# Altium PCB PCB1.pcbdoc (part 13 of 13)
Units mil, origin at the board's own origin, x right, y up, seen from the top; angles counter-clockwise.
Board outline 5895.51 x 5895.51 mil, 8 copper layers (Top Layer, L2_GND1, L3_SIG1, L4_GND2, L5_PWR, L6_SIG2, L7_GND3, Bottom Layer), stack 63.761 mil thick; 673 components, 558 nets, 2797 pads, 1861 vias.
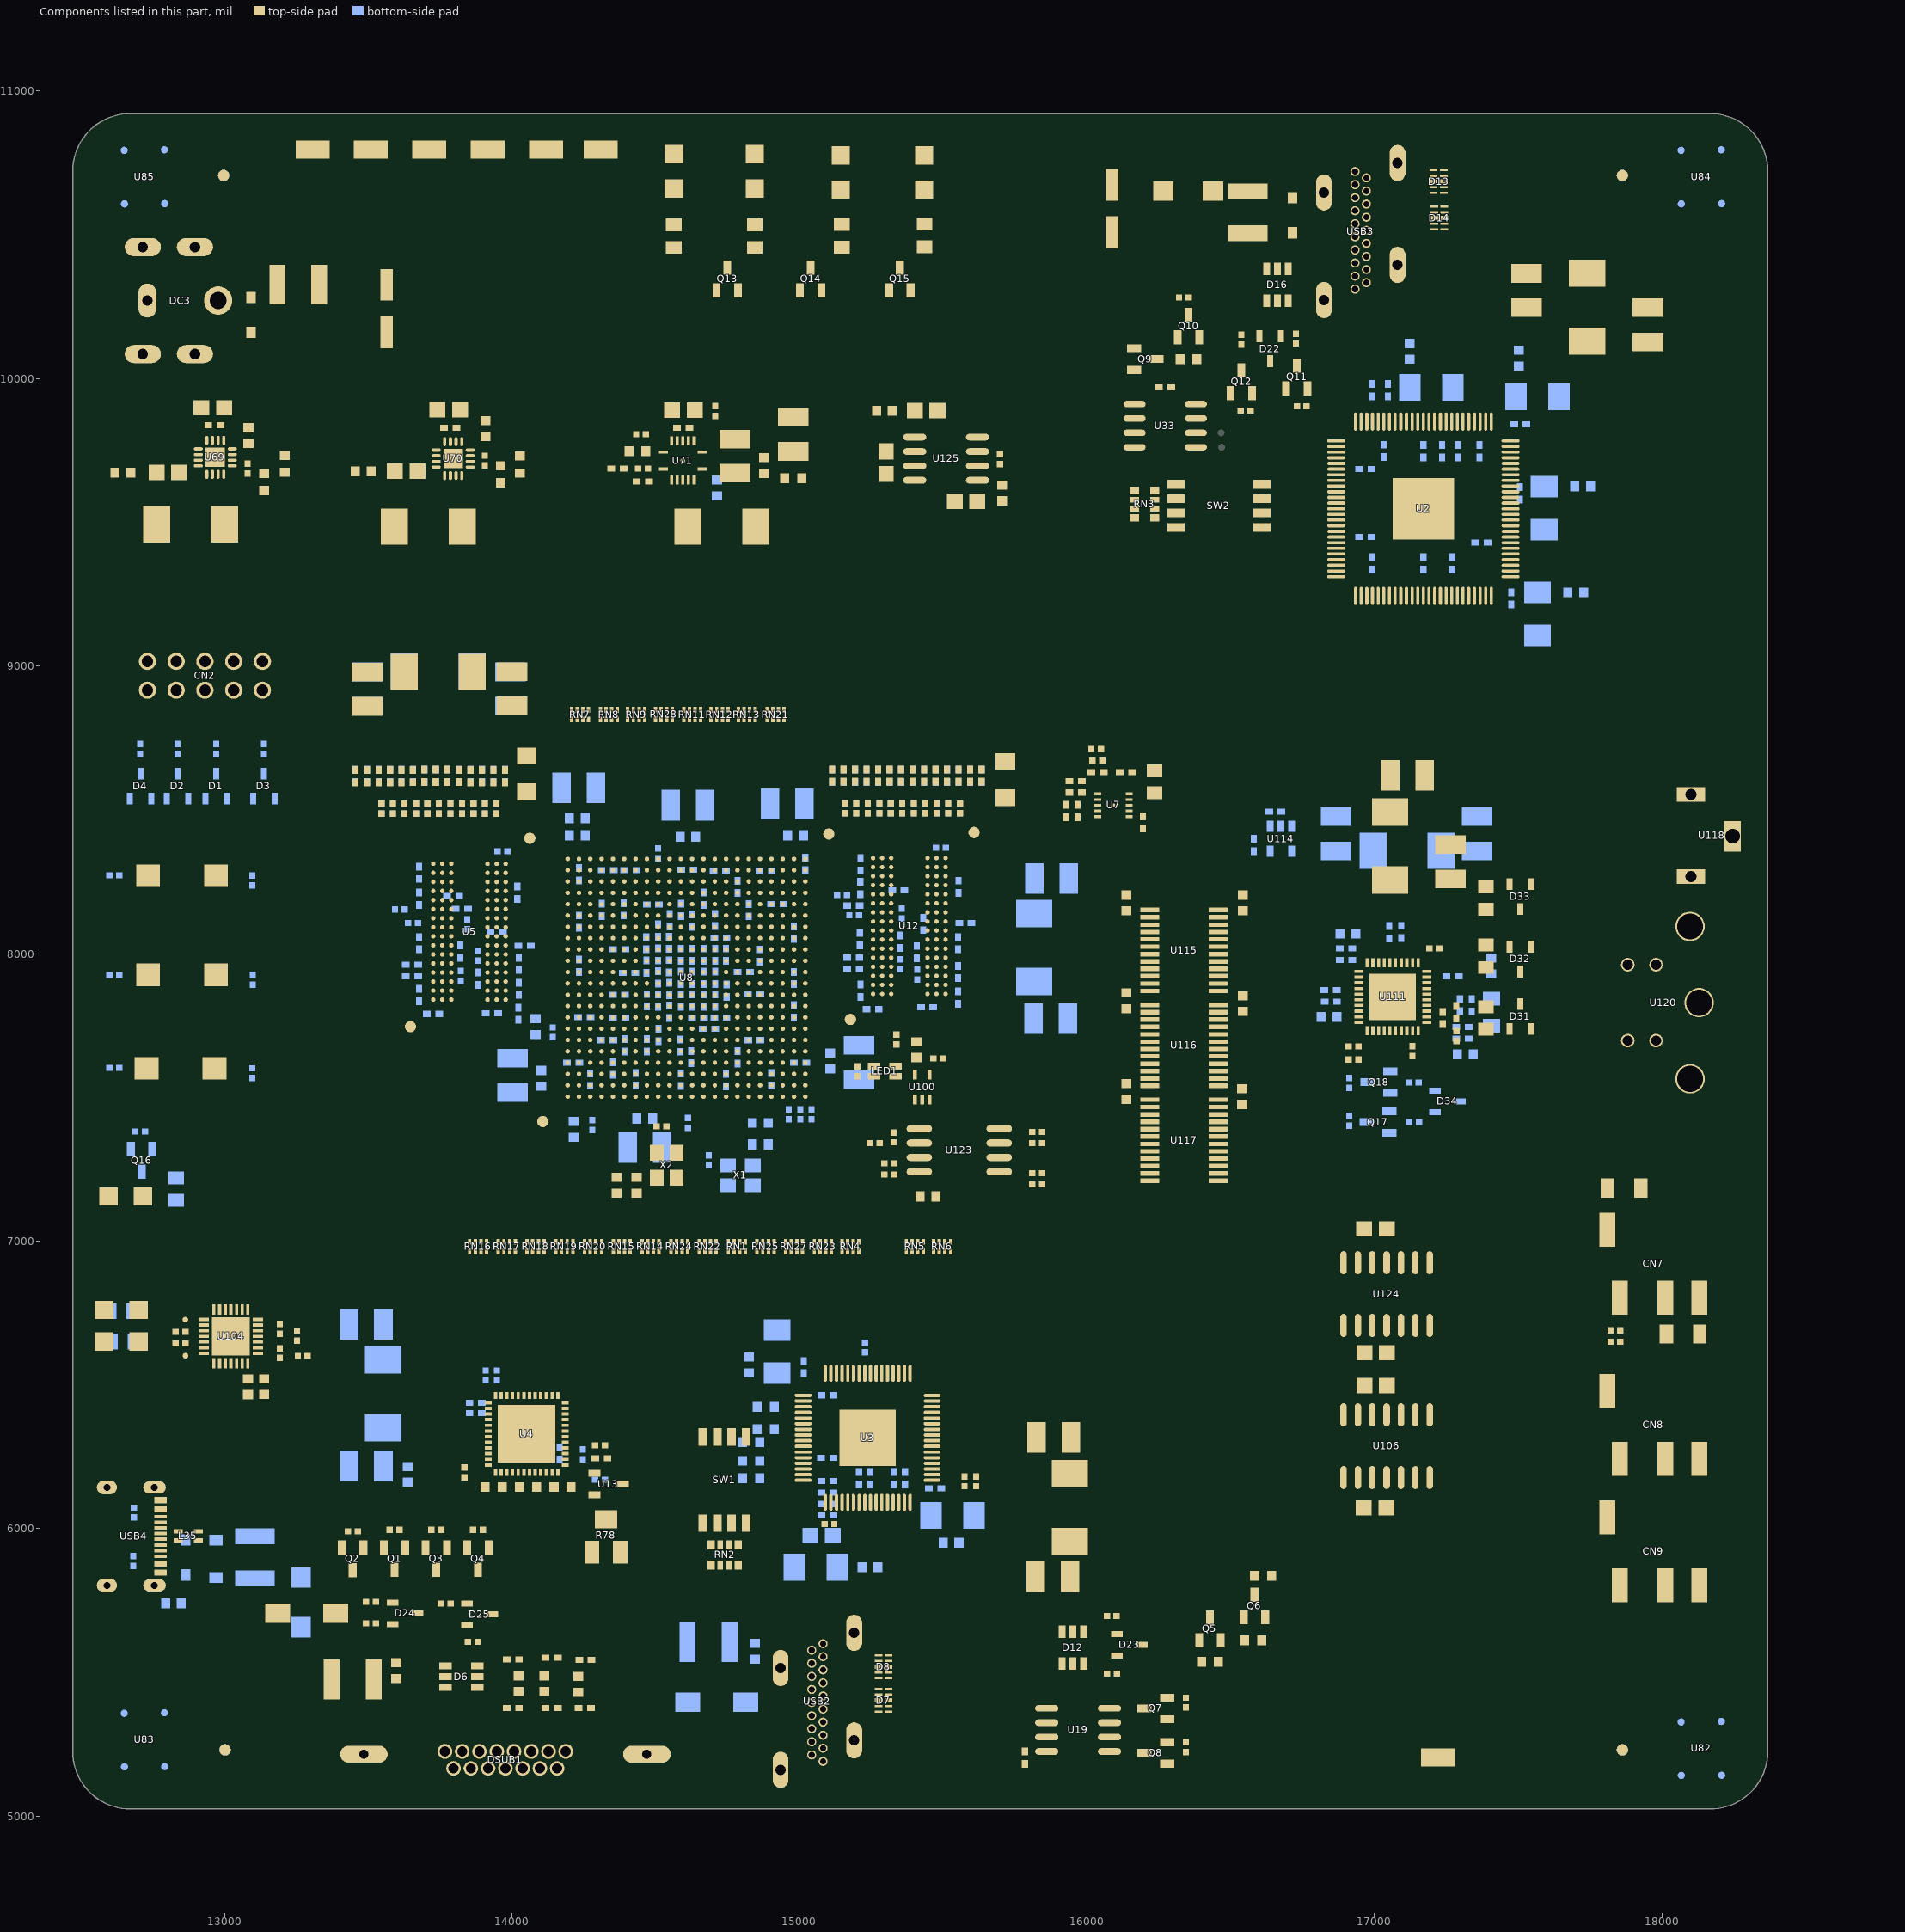
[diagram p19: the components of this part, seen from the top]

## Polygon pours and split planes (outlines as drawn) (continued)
FPGA_3V3 on Top Layer (solid, remove dead copper, pour order 248): 44 vertices, not listed, extent 13951.36,7055 15457.36,7588
VCC_1V5 on L5_PWR (solid, remove dead copper): 27 vertices, not listed, extent 14858.1,7420 16419.36,8688
VCC_1V5 on L5_PWR (solid, remove dead copper): 41 vertices, not listed, extent 13362.36,8615 15999.18,9852
VTT_DDR3 on Top Layer (solid, remove dead copper, pour order 254): 14010.1,8511.16 15163.52,8511.16 15168.36,8516 15136.02,8548.34 15136.02,8609.82 14002.54,8609.82 13997.36,8615 13997.36,8523.9
GND on Bottom Layer (solid, remove dead copper, pour order 372): 14724.36,7158 14870.36,7158 14876.36,7164 14876.36,7362.23 14880.74,7366.62 14934.74,7366.62 15032.36,7269 15215.26,7269 15215.26,7132.09 14729.45,7132.09 14724.36,7127
GND on Bottom Layer (solid, remove dead copper, pour order 374): 19 vertices, not listed, extent 14614.36,8368 15138.87,8737.52
GND on Bottom Layer (solid, remove dead copper, pour order 376): 14075.42,8623.83 14130.39,8623.83 14130.39,8382.52 14137.43,8375.49 14226.2,8375.49 14228.9,8378.19 14228.9,8637.45 14138.36,8728 14068.88,8728 14068.88,8630.36
GND on Bottom Layer (solid, remove dead copper, pour order 378): 14560.16,7463.2 14567.36,7456 14567.36,7149 14562.36,7144 13784.36,7144 13780.36,7140 13780.36,7225 13784.36,7229 14469.28,7229 14475.36,7235.08 14475.36,7459.36 14477.26,7463.2
VCC_AUX on Bottom Layer (solid, remove dead copper, pour order 380): 14238.39,8383.06 14328.03,8383.06 14328.03,8740.33 14317.36,8751 14188.36,8751 14186.36,8753 14186.36,9080 14145.66,9080 14145.66,8744.69 14205.36,8685 14239.36,8685 14239.36,8384.03
VCC_AUX on L3_SIG1 (solid, remove dead copper): 14439.12,8120.4 14783.2,8120.4 14783.2,7940.28 14439.12,7940.28
VCC_AUX on L5_PWR (solid, remove dead copper): 14238.39,8383.06 14424.26,8383.06 14436.84,8370.49 14436.84,8062.48 14436.36,8062 14489.36,8062 14491.36,8060 14491.36,8505.92 14478.68,8518.59 14232.36,8518.59 14238.39,8512.55
VDD_DDR3 on L5_PWR (solid, remove dead copper): 15550.36,8353 15746.64,8353 15746.64,8091.5 15550.36,8091.5
VDD_DDR3 on L5_PWR (solid, remove dead copper): 18 vertices, not listed, extent 13659.74,7795.97 14178.36,9189.39
VDD_DDR3 on Top Layer (solid, remove dead copper, pour order 274): 19 vertices, not listed, extent 14050.36,8099.88 16552.67,9195.38
GND on Top Layer (solid, remove dead copper, pour order 276): 18 vertices, not listed, extent 14414.26,7125.9 15214.94,7456
GND on Bottom Layer (solid, remove dead copper, pour order 394): 14627.36,6731 14998.47,6731 14998.47,6672.7 14627.36,6672.7
410_DVDD on Bottom Layer (solid, remove dead copper, pour order 396): 24 vertices, not listed, extent 15037.51,6230 15131.36,6501
410_TVDD on Bottom Layer (solid, remove dead copper, pour order 398): 15190.29,6164.93 15385,6164.93 15385,6125.35 15190.29,6125.35
GND on Bottom Layer (solid, remove dead copper, pour order 400): 14954.36,5806 15065.36,5806 15066.36,5805 15077.36,5816 15077.36,6050.28 15089.72,6062.64 15089.72,6188.28 14983.64,6188.28 14980.36,6185 14980.36,5931 14968.36,5919 14889.36,5919 14889.36,5810 14889.41,5802 14950.36,5802
GND on Top Layer (solid, remove dead copper, pour order 286): 13004.56,10184.84 13253.36,10184.84 13253.36,10037 13004.56,10037
GND on Bottom Layer (solid, remove dead copper, pour order 404): 10961.36,12250 20212.36,12250 20212.36,3000 10961.36,3000
GND on Top Layer (solid, remove dead copper, pour order 290): 25 vertices, not listed, extent 13770.36,7136 14546.36,7465

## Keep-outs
Board Outline Layer:
  region: 18181.49,10531.81 18321.67,10531.81 18321.67,9631.72 18181.49,9631.72
  lines w10: 12472.36,5225.49 ccw(c12672.36,5225.49) 12672.36,5025.49 18167.87,5025.49 ccw(c18167.87,5225.49) 18367.87,5225.49 18367.87,10721 ccw(c18167.87,10721) 18167.87,10921 12672.36,10921 ccw(c12672.36,10721) 12472.36,10721 12472.36,5225.49

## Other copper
Top Layer:
  drawing of 3039 lines, arcs and shapes, not listed
  text "1" at 18230.36,10404 h120
L2_GND1:
  text "2" at 18230.36,10294 h120
L3_SIG1:
  drawing of 203 lines, arcs and shapes, not listed
  text "3" at 18230.36,10184 h120
L4_GND2:
  region net 401_DVDD: 16716.6,9893.07 16708.52,9872.87 ccw(c16729.07,9893.41) 16719.74,9865.89 16727.62,9877.81 ccw(c16674.88,9851.35)
  text "4" at 18230.36,10074 h120
L5_PWR:
  region net VCC_1V2: 14452.99,8023.92 14460.06,8030.99 14459.46,8031.52 14458.88,8031.91 14457.86,8032.51 14457.45,8032.83 14457.12,8033.23 14456.89,8033.78 14456.77,8034.53 14449.45,8027.21 14450.2,8027.1 14450.75,8026.87 14451.16,8026.54 14451.48,8026.13 14452.07,8025.11 14452.47,8024.53
  region net VCC_1V2: 14486.15,8004.91 14479.08,7997.84 14479.68,7997.31 14480.26,7996.92 14481.28,7996.32 14481.7,7996 14482.03,7995.6 14482.25,7995.05 14482.37,7994.3 14489.69,8001.62 14488.94,8001.73 14488.39,8001.96 14487.99,8002.29 14487.67,8002.7 14487.07,8003.72 14486.68,8004.3
  region net FPGA_3V3: 14334.89,7590.87 14341.96,7597.94 14341.36,7598.47 14340.78,7598.86 14339.76,7599.46 14339.35,7599.78 14339.02,7600.18 14338.79,7600.73 14338.67,7601.48 14331.35,7594.16 14332.1,7594.05 14332.65,7593.82 14333.06,7593.49 14333.38,7593.08 14333.97,7592.06 14334.37,7591.48
  region net VCC_AUX: 14775.01,8076.58 14767.94,8083.65 14767.42,8083.04 14767.03,8082.46 14766.43,8081.44 14766.11,8081.03 14765.7,8080.7 14765.15,8080.47 14764.4,8080.36 14771.72,8073.04 14771.84,8073.79 14772.07,8074.34 14772.4,8074.74 14772.81,8075.06 14773.83,8075.66 14774.41,8076.05
  region net VCC_AUX: 14794.02,8227.84 14801.09,8220.77 14801.62,8221.38 14802.01,8221.96 14802.61,8222.98 14802.93,8223.39 14803.33,8223.72 14803.88,8223.95 14804.63,8224.06 14797.31,8231.38 14797.2,8230.63 14796.97,8230.08 14796.64,8229.68 14796.23,8229.36 14795.2,8228.76 14794.63,8228.37
  region net VCC_AUX: 14767.05,8082.76 14774.12,8075.69 14777.66,8086.29 14787.36,8102.01
  region net VDD_DDR3_REF: 15099.36,8321.65 15099.36,8336.65 ccw(c15099.36,8427.9) 15159.36,8359.15 15159.36,8299.15 ccw(c15099.36,8230.4)
  text "5" at 18230.36,9964 h120
L6_SIG2:
  drawing of 394 lines, arcs and shapes, not listed
  text "6" at 18230.36,9854 h120
L7_GND3:
  text "7" at 18230.36,9744 h120
Bottom Layer:
  drawing of 999 lines, arcs and shapes, not listed
  text "8" at 18280.19,9634.54 h120

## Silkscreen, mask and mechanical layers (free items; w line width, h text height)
Top Silkscreen Layer:
  drawing of 43 lines, arcs and shapes, not listed
  text "DVI_IN" at 16325.06,10727.32 h120
  text "5V" at 14767.27,10641.73 h120 r90
  text "1V5" at 15347.27,10593.55 h120 r90
  text "3V3" at 15052.27,10588.55 h120 r90
  text "1V2" at 15637.27,10588.55 h120 r90
  text "5V" at 13574.92,10568.08 h120 r90
  text "1V2" at 14192.79,10491.87 h120 r90
  text "3V3" at 13779.26,10488.91 h120 r90
  text "1V5" at 13991.27,10488.55 h120 r90
  text "N5V" at 14381.61,10479.35 h120 r90
  text "GND" at 13388.18,10453.36 h120 r90
  text "5V_IN" at 12483.36,9900 h120
  text "ST  / OCK_INV / DFO / PIXS" at 15934.36,9469 h45
  text "0" at 16549.36,9353 h60
  text "1" at 16345.36,9349 h60
  text "JTAG" at 12782.36,8601 h120
  text "CVBS" at 18001.06,8258.32 h120 r90
  text "MENU" at 13044.45,8198.09 h120
  text "+" at 13072.36,7846 h120
  text "S-VIDEO" at 17794.9,7559.71 h120 r90
  text "-" at 13073.08,7528.09 h120
  text "RX" at 12629.36,6810 h100
  text "Aduio_IN" at 17726.83,6703.74 h120 r90
  text "TX" at 12630.36,6478 h100
  text "0" at 14543.36,6273 h60
  text "1" at 14559.36,6042 h60
  text "RSET" at 14431.36,5939 h45
  text "Aduio_OUT" at 17735.47,5802.13 h120 r90
  text "MSEN / ISEL / DSEL / BSEL" at 14828.36,5731 h45 r90
  text "USB_UART" at 12487.36,5641 h100
  text "GND" at 17323.83,5124.72 h120
  text "DVI_OUT" at 14918.08,5047.52 h120 r90
  text "VGA_OUT" at 13328.26,5024.04 h120 r90
Bottom Silkscreen Layer:
  lines w10: 14155.36,7499 14156.36,7500 ; 14156.36,7662.64 14156.36,7500 ; 14164.36,7797.17 14164.36,8336 14167.36,8339 14418.36,8339 14419.36,8338 ; 14469.36,8299 14472.36,8302 14538.36,8302 14557.84,8321.48 14557.84,8359 14563.84,8365 15037.36,8365 ; 14781.36,8379 14781.36,8681 14891.36,8681 15065.36,8855 ; 15016.36,7744 15022.36,7750 15022.36,7953 ; 15027.36,8027 15028.36,8028 15028.36,8174 ; 15046.36,8248 15048.36,8250 15048.36,8340 ; 15049.36,7658 15049.36,7501 15050.36,7500 14156.36,7500 ; 15065.36,8855 15924.36,8855 15924.36,9644 15065.36,9644 15065.36,8855
  text "A" at 15050.36,8848 h80
  text "A" at 14205.36,7496 h80
  text "US_VIO_V1.0 / 2024.5.25 / BY EE" at 16402.36,6666 h120
Document Layer:
  lines w10: 20966.53,5595.13 25954.97,5595.13 ; 20966.53,5605.13 20966.53,10623.7 25954.97,10623.7 25954.97,5605.13 ; 20966.53,5823.7 25954.97,5823.7 ; 20966.53,6052.27 25954.97,6052.27 ; 20966.53,6280.84 25954.97,6280.84 ; 20966.53,6509.42 25954.97,6509.42 ; 20966.53,6737.99 25954.97,6737.99 ; 20966.53,6966.56 25954.97,6966.56 ; 20966.53,7195.13 25954.97,7195.13 ; 20966.53,7423.7 25954.97,7423.7 ; 20966.53,7652.27 25954.97,7652.27 ; 20966.53,7880.84 25954.97,7880.84 ; 20966.53,8109.42 25954.97,8109.42 ; 20966.53,8337.99 25954.97,8337.99 ; 20966.53,8566.56 25954.97,8566.56 ; 20966.53,8795.13 25954.97,8795.13 ; 20966.53,9023.7 25954.97,9023.7 ; 20966.53,9252.27 25954.97,9252.27 ; 20966.53,9480.84 25954.97,9480.84 ; 20966.53,9709.42 25954.97,9709.42 ; 20966.53,9937.99 25954.97,9937.99 ; 20966.53,10166.56 25954.97,10166.56 ; 20966.53,10395.13 25954.97,10395.13 ; 21723.69,5605.13 21723.69,10623.7 ; 22839.54,5605.13 22839.54,10623.7 ; 23966.4,5605.13 23966.4,10623.7 ; 24629.26,5605.13 24629.26,10623.7 ; 25292.12,5605.13 25292.12,10623.7
  text "图层" at 21080.82,10509.42 h80
  text "类型" at 21837.97,10509.42 h80
  text "材质" at 22953.83,10509.42 h80
  text "厚度(mm)" at 24080.69,10509.42 h80
  text "介电常数" at 24743.54,10509.42 h80
  text "损耗切线" at 25406.4,10509.42 h80
  text "顶层丝印层" at 21080.82,10280.84 h80
  text "TOP_SILK" at 21837.97,10280.84 h80
  text "-" at 22953.83,10280.84 h80
  text "0" at 24080.69,10280.84 h80
  text "0" at 24743.54,10280.84 h80
  text "0" at 25406.4,10280.84 h80
  text "顶层锡膏层" at 21080.82,10052.27 h80
  text "TOP_PASTE_MASK" at 21837.97,10052.27 h80
  text "-" at 22953.83,10052.27 h80
  text "0" at 24080.69,10052.27 h80
  text "0" at 24743.54,10052.27 h80
  text "0" at 25406.4,10052.27 h80
  text "顶层阻焊层" at 21080.82,9823.7 h80
  text "TOP_SOLDER_MASK" at 21837.97,9823.7 h80
  text "0" at 24080.69,9823.7 h80
  text "0" at 24743.54,9823.7 h80
  text "0" at 25406.4,9823.7 h80
  text "顶层" at 21080.82,9595.13 h80
  text "TOP" at 21837.97,9595.13 h80
  text "外层铜厚1oz" at 22953.83,9595.13 h80
  text "0.035" at 24080.69,9595.13 h80
  text "0" at 24743.54,9595.13 h80
  text "0" at 25406.4,9595.13 h80
  text "Dielectric1" at 21080.82,9366.56 h80
  text "SUBSTRATE" at 21837.97,9366.56 h80
  text "1080 RC67% 3.3mil" at 22953.83,9366.56 h80
  text "0.076" at 24080.69,9366.56 h80
  text "0" at 24743.54,9366.56 h80
  text "0" at 25406.4,9366.56 h80
  text "L2_GND1" at 21080.82,9137.99 h80
  text "SIGNAL" at 21837.97,9137.99 h80
  text "内层铜厚" at 22953.83,9137.99 h80
  text "0.015" at 24080.69,9137.99 h80
  text "0" at 24743.54,9137.99 h80
  text "0" at 25406.4,9137.99 h80
  text "Dielectric2" at 21080.82,8909.42 h80
  text "SUBSTRATE" at 21837.97,8909.42 h80
  text "0.3mm H/HOZ 不含铜" at 22953.83,8909.42 h80
  text "0.3" at 24080.69,8909.42 h80
  text "0" at 24743.54,8909.42 h80
  text "0" at 25406.4,8909.42 h80
  text "L3_SIG1" at 21080.82,8680.84 h80
  text "SIGNAL" at 21837.97,8680.84 h80
  text "内层铜厚" at 22953.83,8680.84 h80
  text "0.015" at 24080.69,8680.84 h80
  text "0" at 24743.54,8680.84 h80
  text "0" at 25406.4,8680.84 h80
  text "Dielectric3" at 21080.82,8452.27 h80
  text "SUBSTRATE" at 21837.97,8452.27 h80
  text "7628 RC49% 8.6mil" at 22953.83,8452.27 h80
  text "0.203" at 24080.69,8452.27 h80
  text "0" at 24743.54,8452.27 h80
  text "0" at 25406.4,8452.27 h80
  text "L4_GND2" at 21080.82,8223.7 h80
  text "SIGNAL" at 21837.97,8223.7 h80
  text "内层铜厚" at 22953.83,8223.7 h80
  text "0.015" at 24080.69,8223.7 h80
  text "0" at 24743.54,8223.7 h80
  text "0" at 25406.4,8223.7 h80
  text "Dielectric4" at 21080.82,7995.13 h80
  text "SUBSTRATE" at 21837.97,7995.13 h80
  text "0.3mm H/HOZ 不含铜" at 22953.83,7995.13 h80
  text "0.3" at 24080.69,7995.13 h80
  text "0" at 24743.54,7995.13 h80
  text "0" at 25406.4,7995.13 h80
  text "L5_PWR" at 21080.82,7766.56 h80
  text "SIGNAL" at 21837.97,7766.56 h80
  text "内层铜厚" at 22953.83,7766.56 h80
  text "0.015" at 24080.69,7766.56 h80
  text "0" at 24743.54,7766.56 h80
  text "0" at 25406.4,7766.56 h80
  text "Dielectric5" at 21080.82,7537.99 h80
  text "SUBSTRATE" at 21837.97,7537.99 h80
  text "7628 RC49% 8.6mil" at 22953.83,7537.99 h80
  text "0.203" at 24080.69,7537.99 h80
  text "0" at 24743.54,7537.99 h80
  text "0" at 25406.4,7537.99 h80
  text "L6_SIG2" at 21080.82,7309.42 h80
  text "SIGNAL" at 21837.97,7309.42 h80
  text "内层铜厚" at 22953.83,7309.42 h80
  text "0.015" at 24080.69,7309.42 h80
  text "0" at 24743.54,7309.42 h80
  text "0" at 25406.4,7309.42 h80
  text "Dielectric6" at 21080.82,7080.84 h80
  text "SUBSTRATE" at 21837.97,7080.84 h80
  text "0.3mm H/HOZ 不含铜" at 22953.83,7080.84 h80
  text "0.3" at 24080.69,7080.84 h80
  text "0" at 24743.54,7080.84 h80
  text "0" at 25406.4,7080.84 h80
  text "L7_GND3" at 21080.82,6852.27 h80
  text "SIGNAL" at 21837.97,6852.27 h80
  text "内层铜厚" at 22953.83,6852.27 h80
  text "0.015" at 24080.69,6852.27 h80
  text "0" at 24743.54,6852.27 h80
  text "0" at 25406.4,6852.27 h80
  text "Dielectric7" at 21080.82,6623.7 h80
  text "SUBSTRATE" at 21837.97,6623.7 h80
  text "1080 RC67% 3.3mil" at 22953.83,6623.7 h80
  text "0.076" at 24080.69,6623.7 h80
  text "0" at 24743.54,6623.7 h80
  text "0" at 25406.4,6623.7 h80
  text "底层" at 21080.82,6395.13 h80
  text "BOTTOM" at 21837.97,6395.13 h80
  text "外层铜厚1oz" at 22953.83,6395.13 h80
  text "0.035" at 24080.69,6395.13 h80
  text "0" at 24743.54,6395.13 h80
  text "0" at 25406.4,6395.13 h80
  text "底层阻焊层" at 21080.82,6166.56 h80
  text "BOT_SOLDER_MASK" at 21837.97,6166.56 h80
  text "0" at 24080.69,6166.56 h80
  text "0" at 24743.54,6166.56 h80
  text "0" at 25406.4,6166.56 h80
  text "底层锡膏层" at 21080.82,5937.99 h80
  text "BOT_PASTE_MASK" at 21837.97,5937.99 h80
  text "-" at 22953.83,5937.99 h80
  text "0" at 24080.69,5937.99 h80
  text "0" at 24743.54,5937.99 h80
  text "0" at 25406.4,5937.99 h80
  text "底层丝印层" at 21080.82,5709.42 h80
  text "BOT_SILK" at 21837.97,5709.42 h80
  text "-" at 22953.83,5709.42 h80
  text "0" at 24080.69,5709.42 h80
  text "0" at 24743.54,5709.42 h80
  text "0" at 25406.4,5709.42 h80
Ratline Layer:
  drawing of 38 lines, arcs and shapes, not listed
  text "Mark" at 3114.29,10142.89 h80
  text "Count" at 3627.34,10142.89 h80
  text "Size" at 4184.1,10142.89 h80
  text "Plated" at 5744.96,10142.89 h80
  text "Shape" at 6320.31,10142.89 h80
  text "Via/Pad" at 6883.77,10142.89 h80
  text "Pad Shape" at 7540.93,10142.89 h80
  text "Layer Pair" at 8296.59,10142.89 h80
  text "1" at 3627.34,9914.32 h80
  text "36.0x78.7mil(0.914x2.000mm)" at 4184.1,9914.32 h80
  text "PTH" at 5744.96,9914.32 h80
  text "Slot" at 6320.31,9914.32 h80
  text "Pad" at 6883.77,9914.32 h80
  text "Oval" at 7540.93,9914.32 h80
  text "Top Layer-Bottom Layer" at 8296.59,9914.32 h80
  text "1" at 3627.34,9685.74 h80
  text "59.1x59.1mil(1.500x1.500mm)" at 4184.1,9685.74 h80
  text "PTH" at 5744.96,9685.74 h80
  text "Round" at 6320.31,9685.74 h80
  text "Pad" at 6883.77,9685.74 h80
  text "Round" at 7540.93,9685.74 h80
  text "Top Layer-Bottom Layer" at 8296.59,9685.74 h80
  text "1" at 3627.34,9457.17 h80
  text "51.2x98.4mil(1.300x2.500mm)" at 4184.1,9457.17 h80
  text "PTH" at 5744.96,9457.17 h80
  text "Slot" at 6320.31,9457.17 h80
  text "Pad" at 6883.77,9457.17 h80
  text "Rectangle" at 7540.93,9457.17 h80
  text "Top Layer-Bottom Layer" at 8296.59,9457.17 h80
  text "2" at 3627.34,9228.6 h80
  text "31.5x126.0mil(0.800x3.200mm)" at 4184.1,9228.6 h80
  text "PTH" at 5744.96,9228.6 h80
  text "Slot" at 6320.31,9228.6 h80
  text "Pad" at 6883.77,9228.6 h80
  text "Oval" at 7540.93,9228.6 h80
  text "Top Layer-Bottom Layer" at 8296.59,9228.6 h80
  text "2" at 3627.34,9000.03 h80
  text "23.6x59.1mil(0.600x1.500mm)" at 4184.1,9000.03 h80
  text "PTH" at 5744.96,9000.03 h80
  text "Slot" at 6320.31,9000.03 h80
  text "Pad" at 6883.77,9000.03 h80
  text "Oval" at 7540.93,9000.03 h80
  text "Top Layer-Bottom Layer" at 8296.59,9000.03 h80
  text "2" at 3627.34,8771.46 h80
  text "23.6x47.2mil(0.600x1.200mm)" at 4184.1,8771.46 h80
  text "PTH" at 5744.96,8771.46 h80
  text "Slot" at 6320.31,8771.46 h80
  text "Pad" at 6883.77,8771.46 h80
  text "Oval" at 7540.93,8771.46 h80
  text "Top Layer-Bottom Layer" at 8296.59,8771.46 h80
  text "2" at 3627.34,8542.89 h80
  text "39.4x86.6mil(1.000x2.200mm)" at 4184.1,8542.89 h80
  text "PTH" at 5744.96,8542.89 h80
  text "Slot" at 6320.31,8542.89 h80
  text "Pad" at 6883.77,8542.89 h80
  text "Rectangle" at 7540.93,8542.89 h80
  text "Top Layer-Bottom Layer" at 8296.59,8542.89 h80
  text "3" at 3627.34,8314.32 h80
  text "90.6x90.6mil(2.300x2.300mm)" at 4184.1,8314.32 h80
  text "PTH" at 5744.96,8314.32 h80
  text "Round" at 6320.31,8314.32 h80
  text "Pad" at 6883.77,8314.32 h80
  text "Round" at 7540.93,8314.32 h80
  text "Top Layer-Bottom Layer" at 8296.59,8314.32 h80
  text "4" at 3627.34,8085.74 h80
  text "36.0x94.5mil(0.914x2.400mm)" at 4184.1,8085.74 h80
  text "PTH" at 5744.96,8085.74 h80
  text "Slot" at 6320.31,8085.74 h80
  text "Pad" at 6883.77,8085.74 h80
  text "Oval" at 7540.93,8085.74 h80
  text "Top Layer-Bottom Layer" at 8296.59,8085.74 h80
  text "A" at 3114.29,7857.17 h80
  text "8" at 3627.34,7857.17 h80
  text "35.4x106.3mil(0.900x2.700mm)" at 4184.1,7857.17 h80
  text "PTH" at 5744.96,7857.17 h80
  text "Slot" at 6320.31,7857.17 h80
  text "Pad" at 6883.77,7857.17 h80
  text "Oval" at 7540.93,7857.17 h80
  text "Top Layer-Bottom Layer" at 8296.59,7857.17 h80
  text "B" at 3114.29,7628.6 h80
  text "10" at 3627.34,7628.6 h80
  text "12.0mil(0.305mm)" at 4184.1,7628.6 h80
  text "PTH" at 5744.96,7628.6 h80
  text "Round" at 6320.31,7628.6 h80
  text "Via" at 6883.77,7628.6 h80
  text "Top Layer-Bottom Layer" at 8296.59,7628.6 h80
  text "C" at 3114.29,7400.03 h80
  text "10" at 3627.34,7400.03 h80
  text "39.4x39.4mil(1.000x1.000mm)" at 4184.1,7400.03 h80
  text "PTH" at 5744.96,7400.03 h80
  text "Round" at 6320.31,7400.03 h80
  text "Pad" at 6883.77,7400.03 h80
  text "Round" at 7540.93,7400.03 h80
  text "Top Layer-Bottom Layer" at 8296.59,7400.03 h80
  text "D" at 3114.29,7171.46 h80
  text "19" at 3627.34,7171.46 h80
  text "35.4x35.4mil(0.900x0.900mm)" at 4184.1,7171.46 h80
  text "PTH" at 5744.96,7171.46 h80
  text "Round" at 6320.31,7171.46 h80
  text "Pad" at 6883.77,7171.46 h80
  text "Round" at 7540.93,7171.46 h80
  text "Top Layer-Bottom Layer" at 8296.59,7171.46 h80
  text "E" at 3114.29,6942.89 h80
  text "38" at 3627.34,6942.89 h80
  text "21.7x21.7mil(0.550x0.550mm)" at 4184.1,6942.89 h80
  text "PTH" at 5744.96,6942.89 h80
  text "Round" at 6320.31,6942.89 h80
  text "Pad" at 6883.77,6942.89 h80
  text "Round" at 7540.93,6942.89 h80
  text "Top Layer-Bottom Layer" at 8296.59,6942.89 h80
  text "F" at 3114.29,6714.32 h80
  text "549" at 3627.34,6714.32 h80
  text "7.9mil(0.200mm)" at 4184.1,6714.32 h80
  text "PTH" at 5744.96,6714.32 h80
  text "Round" at 6320.31,6714.32 h80
  text "Via" at 6883.77,6714.32 h80
  text "Top Layer-Bottom Layer" at 8296.59,6714.32 h80
  text "G" at 3114.29,6485.74 h80
  text "621" at 3627.34,6485.74 h80
  text "15.7mil(0.400mm)" at 4184.1,6485.74 h80
  text "PTH" at 5744.96,6485.74 h80
  text "Round" at 6320.31,6485.74 h80
  text "Via" at 6883.77,6485.74 h80
  text "Top Layer-Bottom Layer" at 8296.59,6485.74 h80
  text "H" at 3114.29,6257.17 h80
  text "681" at 3627.34,6257.17 h80
  text "7.9mil(0.201mm)" at 4184.1,6257.17 h80
  text "PTH" at 5744.96,6257.17 h80
  text "Round" at 6320.31,6257.17 h80
  text "Via" at 6883.77,6257.17 h80
  text "Top Layer-Bottom Layer" at 8296.59,6257.17 h80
